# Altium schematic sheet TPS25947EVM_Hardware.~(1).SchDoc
size 431 x 279 mm; Date: Not shown in title block; ApprovedBy: Not shown in title block; CheckedBy: Not shown in title block; Author: Not shown in title block; CompanyName: Not shown in title block; Engineer: Not shown in title block; Organization: Not shown in title block; Address1: Not shown in title block; Address2: Not shown in title block; Address3: Not shown in title block; Address4: Not shown in title block; DocumentNumber: 3; Revision: Use project parameter SCH_Rev; SheetNumber: 3; SheetTotal: 3; PageSetup: Record=PageOptions¦CenterHorizontal=True¦CenterVertical=True¦PrintScale=1.00¦XCorrection=1.00¦YCorrection=1.00¦PrintKind=0¦BorderSize=5000000¦LeftOffset=0¦BottomOffset=0¦Orientation=2¦PaperLength=1000¦PaperWidth=1000¦Scale=100¦PaperSource=15¦PrintQuality=600¦MediaType=1¦DitherType=10¦PaperKind=Letter¦PrintScaleMode=1
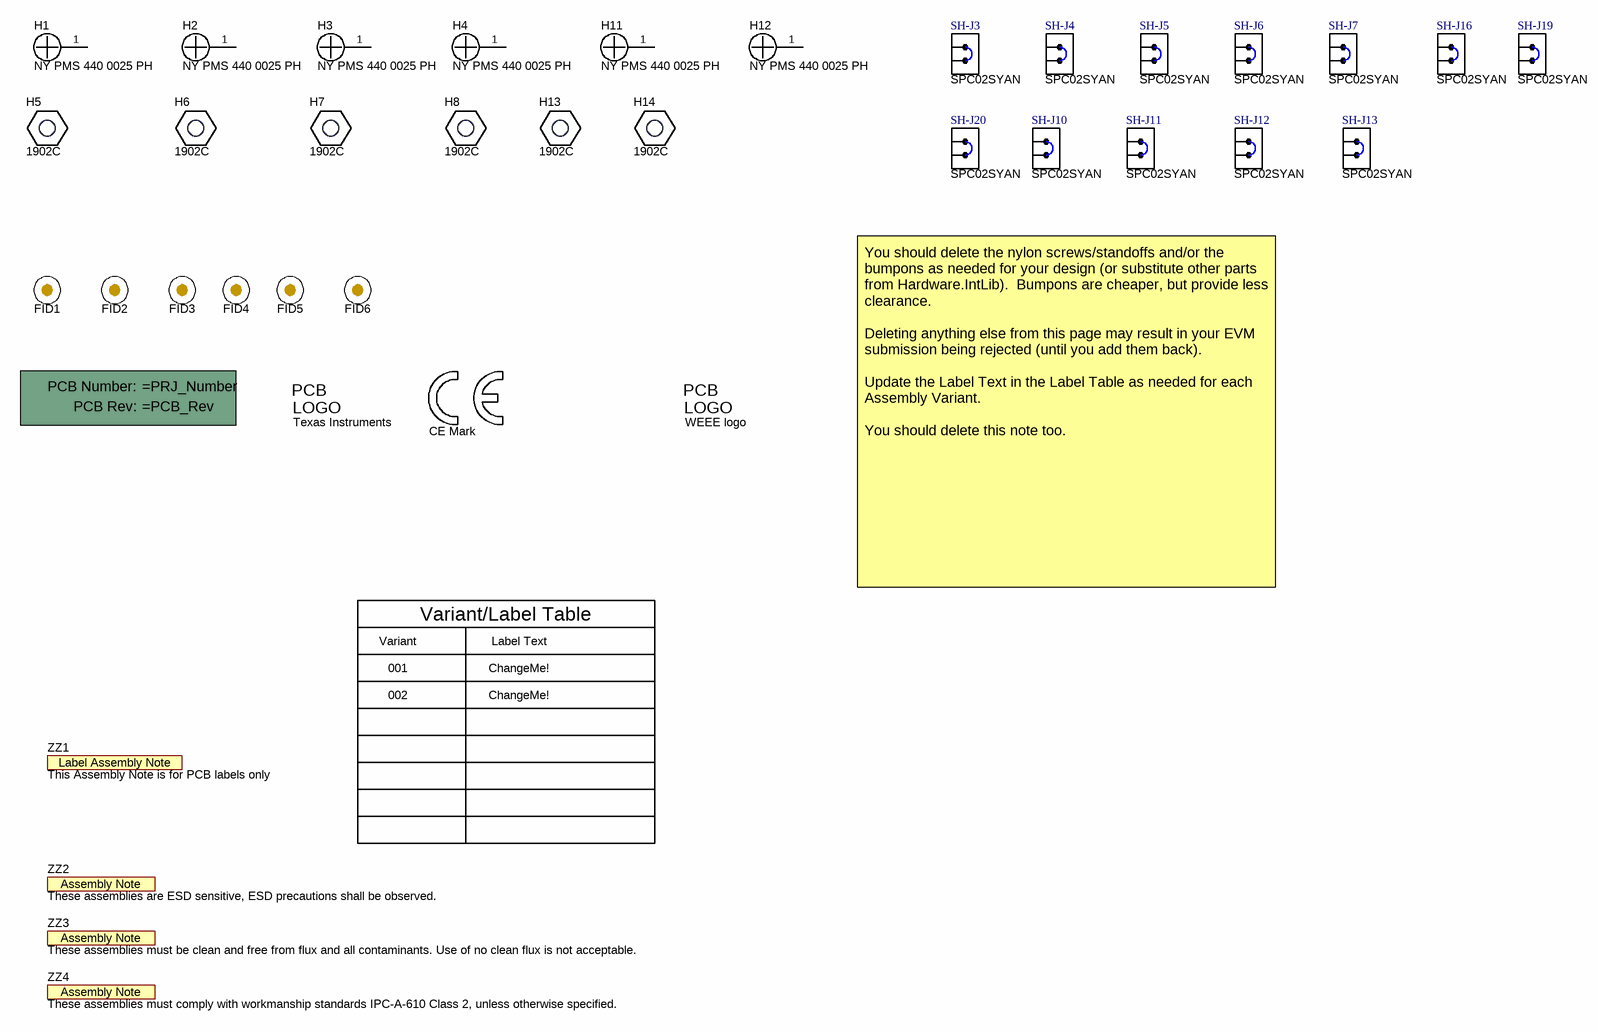
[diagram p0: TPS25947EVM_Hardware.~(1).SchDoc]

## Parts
!PCB  Printed Circuit Board  (value not drawn)  (mechanical)
FID1  Fiducial  [Fiducial10-20]  (value not drawn)
FID2  Fiducial  [Fiducial10-20]  (value not drawn)
FID3  Fiducial  [Fiducial10-20]  (value not drawn)
FID4  Fiducial  [Fiducial10-20]  (value not drawn)
FID5  Fiducial  [Fiducial10-20]  (value not drawn)
FID6  Fiducial  [Fiducial10-20]  (value not drawn)
H1  NY PMS 440 0025 PH  [NY PMS 440 0025 PH]
H2  NY PMS 440 0025 PH  [NY PMS 440 0025 PH]
H3  NY PMS 440 0025 PH  [NY PMS 440 0025 PH]
H4  NY PMS 440 0025 PH  [NY PMS 440 0025 PH]
H5  1902C  [Keystone_1902C]
H6  1902C  [Keystone_1902C]
H7  1902C  [Keystone_1902C]
H8  1902C  [Keystone_1902C]
H11  NY PMS 440 0025 PH  [NY PMS 440 0025 PH]
H12  NY PMS 440 0025 PH  [NY PMS 440 0025 PH]
H13  1902C  [Keystone_1902C]
H14  1902C  [Keystone_1902C]
Logo1  Texas Instruments  [TI_Stacked_Overlay_Small]  (no BOM)
Logo2  CE Mark  [CE_Mark_5mm]  (no BOM)
Logo4  WEEE logo  [WEEE_Minimum]  (no BOM)
SH-J3  SPC02SYAN  [SPC02SYAN]
SH-J4  SPC02SYAN  [SPC02SYAN]
SH-J5  SPC02SYAN  [SPC02SYAN]
SH-J6  SPC02SYAN  [SPC02SYAN]
SH-J7  SPC02SYAN  [SPC02SYAN]
SH-J10  SPC02SYAN  [SPC02SYAN]
SH-J11  SPC02SYAN  [SPC02SYAN]
SH-J12  SPC02SYAN  [SPC02SYAN]
SH-J13  SPC02SYAN  [SPC02SYAN]
SH-J16  SPC02SYAN  [SPC02SYAN]
SH-J19  SPC02SYAN  [SPC02SYAN]
SH-J20  SPC02SYAN  [SPC02SYAN]
ZZ1  This Assembly Note is for PCB labels only  [AssemblyNoteLabel]  (no BOM)
ZZ2  These assemblies are ESD sensitive, ESD precautions shall be observed.  [AssemblyNote]  (no BOM)
ZZ3  These assemblies must be clean and free from flux and all contaminants. Use of no clean flux is not acceptable.  [AssemblyNote]  (no BOM)
ZZ4  These assemblies must comply with workmanship standards IPC-A-610 Class 2, unless otherwise specified.  [AssemblyNote]  (no BOM)

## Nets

Not connected (* = marked no-connect by the designer): H1 1; H2 1; H3 1; H4 1; H11 1; H12 1

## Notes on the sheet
- Variant
- Variant/Label Table
- Label Text
- You should delete the nylon screws/standoffs and/or the bumpons as needed for your design (or substitute other parts from Hardware.IntLib).  Bumpons are cheaper, but provide less clearance.
  Deleting anything else from this page may result in your EVM submission being rejected (until you add them back).
  Update the Label Text in the Label Table as needed for each Assembly Variant.
  You should delete this note too.
- 001
- 002
- ChangeMe!

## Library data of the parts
!PCB = CMP-0003618-2: Manufacturer: Any
FID1-FID6 = CMP-0077181-1: Fiducial mark.  There is nothing to buy or mount.
H1-H4 H11 H12 = CMP-0003617-1: Machine Screw, Round, #4-40 x 1/4, Nylon, Philips panhead; Manufacturer: B&F Fastener Supply; CompType: Hardware
H5-H8 H13 H14 = CMP-0003610-1: Standoff, Hex, 0.5"L #4-40 Nylon; Manufacturer: Keystone; CompType: Hardware
Logo1 = CMP-0074838-1: Texas Instrument Corporate Signature; SymbolCreator: a0412235; Lib Reference: TI_Logo; Library Reference: Logo
Logo2 = CMP-0074844-1: SymbolCreator: a0412235
Logo4 = CMP-0074769-1
SH-J3-SH-J7 SH-J10-SH-J13 SH-J16 SH-J19 SH-J20 = CMP-0003642-1: Shunt, 100mil, Flash Gold, Black; Manufacturer: Sullins Connector Solutions; Value: 1x2
ZZ1 = CMP-0003616-3
ZZ2 = CMP-0077236-1
ZZ3 = CMP-0077237-1
ZZ4 = CMP-0077238-1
